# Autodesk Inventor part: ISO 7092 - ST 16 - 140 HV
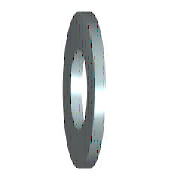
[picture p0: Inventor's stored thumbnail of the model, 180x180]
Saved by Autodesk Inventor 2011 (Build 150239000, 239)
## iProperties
Created: 2009-02
Part Number: ISO 7092 - ST 16 - 140 HV
Material: Stainless Steel
Description: Plain washers-Small series-Product grade A
Document SubType Name: Modeling
Standard: ISO 7092
Designer: 904Chiaki
Standard Revision: Second edition 2000-06-01
Standards Organization: ISO
Language: en-US
Size Designation: ST 16 - 140 HV
Categories: <MemberInstance><Categories><Category DisplayName="Fasteners" InternalName="e4da775c-781d-43d5-af7c-5136215cf5a6" Mnemonic="FSTN"><Category DisplayName="Washers
Density: 8.08 g/cm^3
Mass: 7.8532 g
Surface Area: 11.3097 cm^2
Volume: 0.97193 cm^3
IsCustomPart: 0
Author: 904Chiaki
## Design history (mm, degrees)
body "Solid1"
sketch "Sketch"
  geometry: C1 r 14 at (0, 0); C2 r 8.5 at (0, 0); 1 further point
  constraints: 2 centre point, 2 coincident
  dimensions: "d0" = 17 diameter of C2 (= SD1); "d1" = 28 diameter of C1 (= SD2)
extrude "Body" new body sketch "Sketch" distance "d2" = 2.5 (= SD); taper "d3" = 0 deg
workaxis "Work Axis1"
workplane "Work Plane1"
other parameters: "SD1" = 17 [user parameter; used in 1 equation term], "SD2" = 28 [user parameter; used in 1 equation term], "SD" = 2.5 [user parameter; used in 1 equation term], "d4" = 0, "d5" = 0, "d6" = 0, "d7" = 0, "NND" = 16 [user parameter]
